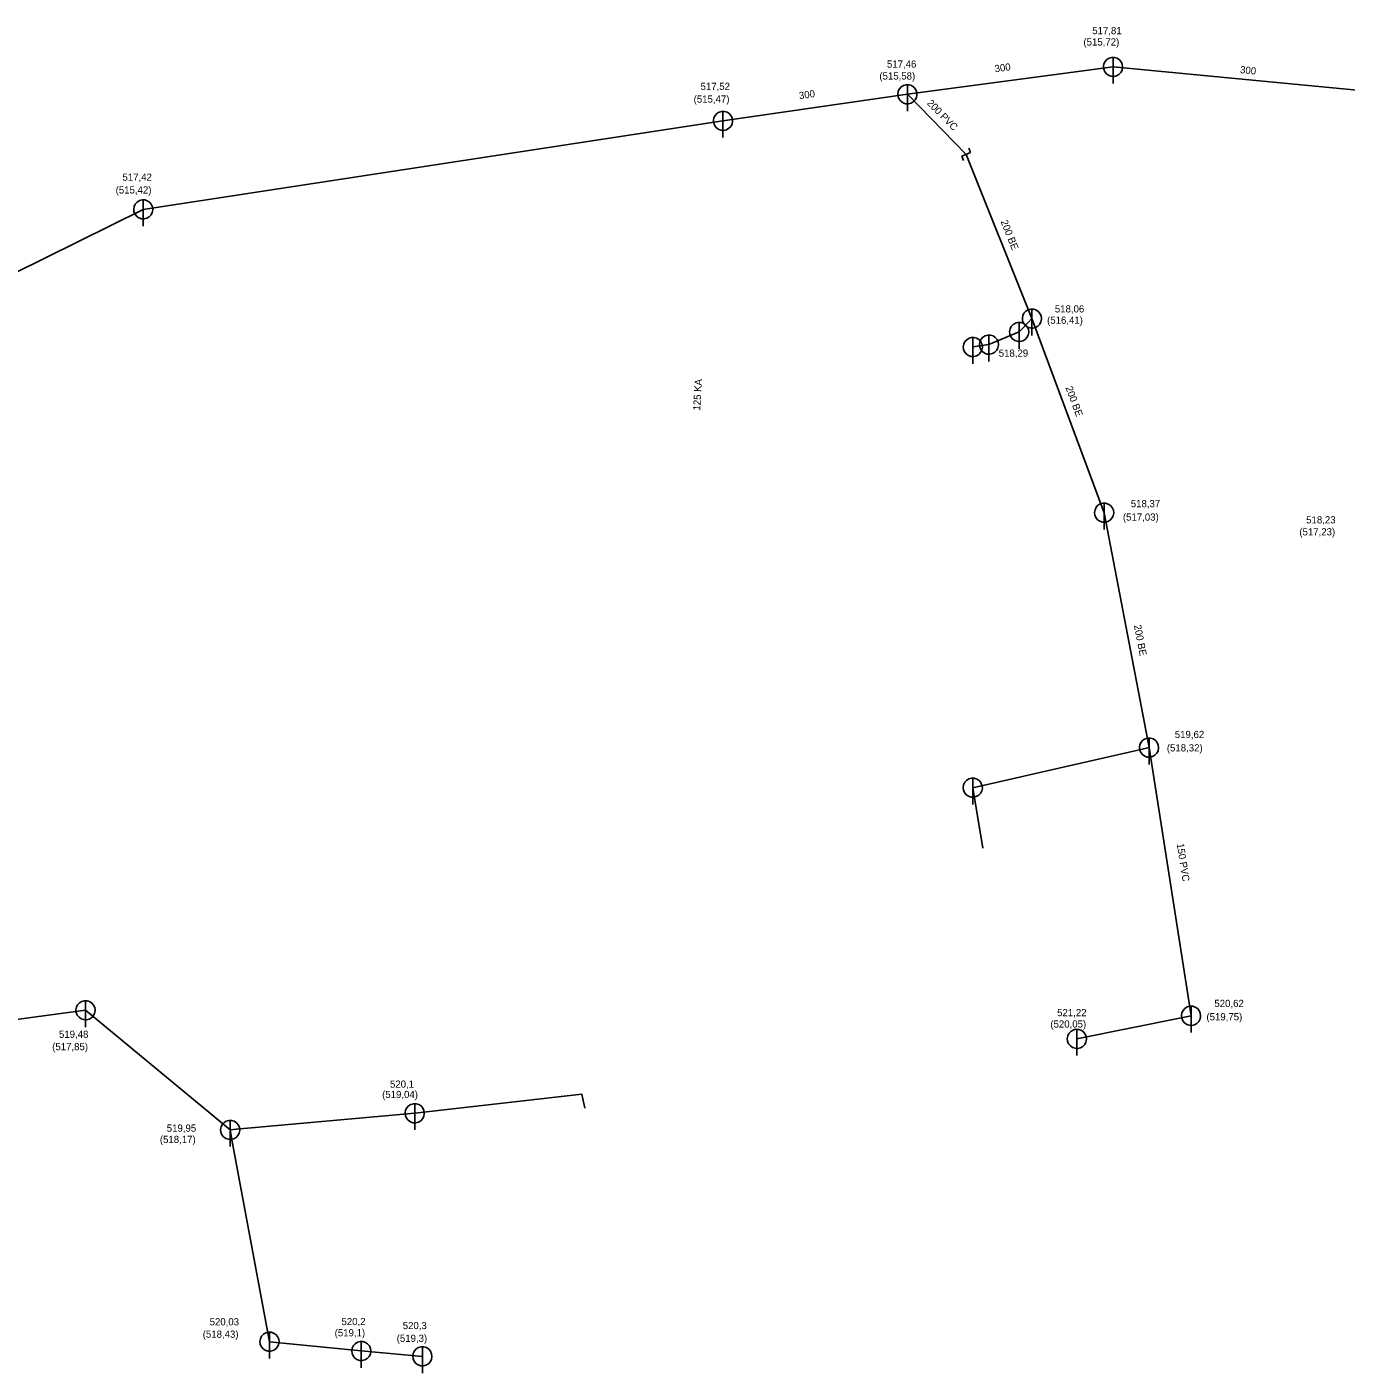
# Model space of a CAD drawing. Extents: x -476058 to -471893, y -1155786 to -1152000.
# Drawn here: x -474134.8 to -473997.2, y -1154043.8 to -1153903.4 of the extents above; entities that cross this region are included whole.
import ezdxf

# ---------------------------------------------------------------- set-up
doc = ezdxf.new("R2010")
doc.units = 0
for name, color, linetype in [('Vrstva 10', 7, 'Continuous'), ('Vrstva 18', 7, 'Continuous'), ('Vrstva 19', 7, 'Continuous'), ('Vrstva 3', 7, 'Continuous'), ('Vrstva 4', 7, 'Continuous'), ('Vrstva 45', 7, 'Continuous'), ('Vrstva 50', 7, 'Continuous'), ('Vrstva 51', 7, 'Continuous')]:
    doc.layers.add(name, color=color, linetype=linetype)

msp = doc.modelspace()

# ---------------------------------------------------------------- linework, layer by layer
at = {"layer": 'Vrstva 10'}
for p, q in [((-474021.48, -1153906.57), (-474021.48, -1153909.32)), ((-474042.93, -1153909.43), (-474042.93, -1153912.18)), ((-474062.16, -1153912.2), (-474062.16, -1153914.95)), ((-474036.33, -1153916.51), (-474036.52, -1153916.05)), ((-474037.26, -1153916.88), (-474036.33, -1153916.51)), ((-474037.26, -1153916.88), (-474037.07, -1153917.35)), ((-474122.62, -1153921.44), (-474122.62, -1153924.19)), ((-474029.94, -1153932.83), (-474029.94, -1153935.58)), ((-474031.27, -1153934.22), (-474031.27, -1153936.97)), ((-474036.1, -1153935.79), (-474036.1, -1153938.54)), ((-474034.42, -1153935.55), (-474034.42, -1153938.3)), ((-474022.41, -1153953.08), (-474022.41, -1153955.83)), ((-474017.73, -1153977.59), (-474017.73, -1153980.34)), ((-474036.11, -1153981.77), (-474036.11, -1153984.52)), ((-474128.64, -1154004.99), (-474128.64, -1154007.74)), ((-474013.35, -1154005.57), (-474013.35, -1154008.32)), ((-474025.25, -1154007.97), (-474025.25, -1154010.72)), ((-474094.31, -1154015.73), (-474094.31, -1154018.48)), ((-474113.56, -1154017.47), (-474113.56, -1154020.22)), ((-474109.45, -1154039.57), (-474109.45, -1154042.32)), ((-474099.88, -1154040.54), (-474099.88, -1154043.29)), ((-474093.51, -1154041.1), (-474093.51, -1154043.84))]:
    msp.add_line(p, q, dxfattribs=at)
for points in [[(-474020.48, -1153907.57), (-474020.52, -1153907.29), (-474020.64, -1153907.03), (-474020.82, -1153906.82), (-474021.05, -1153906.67), (-474021.33, -1153906.58), (-474021.61, -1153906.58), (-474021.88, -1153906.65), (-474022.12, -1153906.8), (-474022.31, -1153907.01), (-474022.43, -1153907.26), (-474022.48, -1153907.54), (-474022.45, -1153907.82), (-474022.34, -1153908.08), (-474022.16, -1153908.3), (-474021.93, -1153908.46), (-474021.66, -1153908.55), (-474021.38, -1153908.57), (-474021.11, -1153908.5), (-474020.86, -1153908.36), (-474020.67, -1153908.15), (-474020.54, -1153907.9), (-474020.48, -1153907.63), (-474020.48, -1153907.57)], [(-474041.93, -1153910.43), (-474041.97, -1153910.15), (-474042.09, -1153909.89), (-474042.27, -1153909.68), (-474042.5, -1153909.52), (-474042.77, -1153909.44), (-474043.06, -1153909.44), (-474043.33, -1153909.51), (-474043.57, -1153909.66), (-474043.76, -1153909.87), (-474043.88, -1153910.12), (-474043.93, -1153910.4), (-474043.9, -1153910.68), (-474043.79, -1153910.94), (-474043.61, -1153911.16), (-474043.38, -1153911.32), (-474043.11, -1153911.41), (-474042.83, -1153911.42), (-474042.55, -1153911.35), (-474042.31, -1153911.21), (-474042.12, -1153911.01), (-474041.99, -1153910.76), (-474041.93, -1153910.48), (-474041.93, -1153910.43)], [(-474061.16, -1153913.2), (-474061.2, -1153912.92), (-474061.32, -1153912.66), (-474061.5, -1153912.45), (-474061.74, -1153912.29), (-474062.01, -1153912.21), (-474062.29, -1153912.21), (-474062.56, -1153912.28), (-474062.8, -1153912.43), (-474062.99, -1153912.64), (-474063.11, -1153912.89), (-474063.16, -1153913.17), (-474063.13, -1153913.45), (-474063.02, -1153913.71), (-474062.84, -1153913.93), (-474062.61, -1153914.09), (-474062.34, -1153914.18), (-474062.06, -1153914.19), (-474061.79, -1153914.12), (-474061.54, -1153913.98), (-474061.35, -1153913.78), (-474061.22, -1153913.53), (-474061.16, -1153913.25), (-474061.16, -1153913.2)], [(-474121.62, -1153922.44), (-474121.66, -1153922.16), (-474121.78, -1153921.9), (-474121.96, -1153921.69), (-474122.2, -1153921.53), (-474122.47, -1153921.45), (-474122.75, -1153921.45), (-474123.02, -1153921.52), (-474123.26, -1153921.67), (-474123.45, -1153921.88), (-474123.57, -1153922.13), (-474123.62, -1153922.41), (-474123.59, -1153922.69), (-474123.48, -1153922.95), (-474123.3, -1153923.17), (-474123.07, -1153923.33), (-474122.8, -1153923.42), (-474122.52, -1153923.43), (-474122.25, -1153923.36), (-474122, -1153923.22), (-474121.81, -1153923.02), (-474121.68, -1153922.77), (-474121.62, -1153922.49), (-474121.62, -1153922.44)], [(-474028.94, -1153933.83), (-474028.98, -1153933.55), (-474029.1, -1153933.29), (-474029.28, -1153933.08), (-474029.52, -1153932.93), (-474029.79, -1153932.84), (-474030.07, -1153932.84), (-474030.34, -1153932.91), (-474030.58, -1153933.06), (-474030.77, -1153933.27), (-474030.89, -1153933.52), (-474030.94, -1153933.8), (-474030.91, -1153934.08), (-474030.8, -1153934.34), (-474030.62, -1153934.56), (-474030.39, -1153934.72), (-474030.12, -1153934.81), (-474029.84, -1153934.83), (-474029.57, -1153934.76), (-474029.32, -1153934.62), (-474029.13, -1153934.41), (-474029, -1153934.16), (-474028.94, -1153933.89), (-474028.94, -1153933.83)], [(-474030.27, -1153935.22), (-474030.31, -1153934.94), (-474030.43, -1153934.68), (-474030.61, -1153934.47), (-474030.85, -1153934.31), (-474031.11, -1153934.23), (-474031.4, -1153934.23), (-474031.67, -1153934.3), (-474031.91, -1153934.45), (-474032.1, -1153934.66), (-474032.22, -1153934.91), (-474032.27, -1153935.19), (-474032.24, -1153935.47), (-474032.13, -1153935.73), (-474031.95, -1153935.95), (-474031.72, -1153936.11), (-474031.45, -1153936.2), (-474031.17, -1153936.22), (-474030.9, -1153936.15), (-474030.65, -1153936.01), (-474030.46, -1153935.8), (-474030.33, -1153935.55), (-474030.27, -1153935.28), (-474030.27, -1153935.22)], [(-474035.1, -1153936.79), (-474035.14, -1153936.52), (-474035.26, -1153936.26), (-474035.44, -1153936.04), (-474035.68, -1153935.89), (-474035.95, -1153935.81), (-474036.23, -1153935.8), (-474036.5, -1153935.88), (-474036.74, -1153936.03), (-474036.93, -1153936.23), (-474037.05, -1153936.49), (-474037.1, -1153936.77), (-474037.07, -1153937.05), (-474036.96, -1153937.31), (-474036.78, -1153937.53), (-474036.55, -1153937.69), (-474036.29, -1153937.78), (-474036, -1153937.79), (-474035.73, -1153937.72), (-474035.48, -1153937.58), (-474035.29, -1153937.38), (-474035.16, -1153937.13), (-474035.1, -1153936.85), (-474035.1, -1153936.79)], [(-474033.42, -1153936.55), (-474033.46, -1153936.27), (-474033.58, -1153936.01), (-474033.76, -1153935.8), (-474033.99, -1153935.64), (-474034.27, -1153935.56), (-474034.55, -1153935.56), (-474034.82, -1153935.63), (-474035.06, -1153935.78), (-474035.25, -1153935.99), (-474035.37, -1153936.24), (-474035.42, -1153936.52), (-474035.39, -1153936.8), (-474035.28, -1153937.06), (-474035.1, -1153937.28), (-474034.87, -1153937.44), (-474034.6, -1153937.53), (-474034.32, -1153937.54), (-474034.05, -1153937.48), (-474033.8, -1153937.33), (-474033.61, -1153937.13), (-474033.48, -1153936.88), (-474033.42, -1153936.6), (-474033.42, -1153936.55)], [(-474021.41, -1153954.08), (-474021.45, -1153953.8), (-474021.57, -1153953.54), (-474021.75, -1153953.33), (-474021.98, -1153953.18), (-474022.26, -1153953.09), (-474022.54, -1153953.09), (-474022.81, -1153953.16), (-474023.05, -1153953.31), (-474023.24, -1153953.52), (-474023.36, -1153953.77), (-474023.41, -1153954.05), (-474023.38, -1153954.33), (-474023.27, -1153954.59), (-474023.09, -1153954.81), (-474022.86, -1153954.97), (-474022.59, -1153955.06), (-474022.31, -1153955.08), (-474022.04, -1153955.01), (-474021.79, -1153954.87), (-474021.6, -1153954.66), (-474021.47, -1153954.41), (-474021.41, -1153954.14), (-474021.41, -1153954.08)], [(-474016.73, -1153978.59), (-474016.77, -1153978.31), (-474016.89, -1153978.05), (-474017.07, -1153977.84), (-474017.3, -1153977.69), (-474017.58, -1153977.6), (-474017.86, -1153977.6), (-474018.13, -1153977.67), (-474018.37, -1153977.82), (-474018.56, -1153978.03), (-474018.68, -1153978.28), (-474018.73, -1153978.56), (-474018.7, -1153978.84), (-474018.59, -1153979.1), (-474018.41, -1153979.32), (-474018.18, -1153979.48), (-474017.91, -1153979.57), (-474017.63, -1153979.59), (-474017.36, -1153979.52), (-474017.11, -1153979.38), (-474016.92, -1153979.17), (-474016.79, -1153978.92), (-474016.73, -1153978.65), (-474016.73, -1153978.59)], [(-474035.11, -1153982.77), (-474035.15, -1153982.5), (-474035.27, -1153982.24), (-474035.45, -1153982.02), (-474035.69, -1153981.87), (-474035.96, -1153981.79), (-474036.24, -1153981.78), (-474036.51, -1153981.86), (-474036.75, -1153982.01), (-474036.94, -1153982.21), (-474037.06, -1153982.47), (-474037.11, -1153982.75), (-474037.08, -1153983.03), (-474036.97, -1153983.29), (-474036.79, -1153983.51), (-474036.56, -1153983.67), (-474036.29, -1153983.76), (-474036.01, -1153983.77), (-474035.74, -1153983.7), (-474035.49, -1153983.56), (-474035.3, -1153983.36), (-474035.17, -1153983.11), (-474035.11, -1153982.83), (-474035.11, -1153982.77)], [(-474127.64, -1154005.99), (-474127.68, -1154005.71), (-474127.8, -1154005.45), (-474127.98, -1154005.24), (-474128.22, -1154005.08), (-474128.48, -1154005), (-474128.77, -1154005), (-474129.04, -1154005.07), (-474129.28, -1154005.22), (-474129.47, -1154005.43), (-474129.59, -1154005.68), (-474129.64, -1154005.96), (-474129.61, -1154006.24), (-474129.5, -1154006.5), (-474129.32, -1154006.72), (-474129.09, -1154006.88), (-474128.82, -1154006.97), (-474128.54, -1154006.99), (-474128.27, -1154006.92), (-474128.02, -1154006.78), (-474127.83, -1154006.57), (-474127.7, -1154006.32), (-474127.64, -1154006.05), (-474127.64, -1154005.99)], [(-474012.35, -1154006.57), (-474012.39, -1154006.29), (-474012.51, -1154006.03), (-474012.69, -1154005.82), (-474012.92, -1154005.67), (-474013.2, -1154005.58), (-474013.48, -1154005.58), (-474013.75, -1154005.65), (-474013.99, -1154005.8), (-474014.18, -1154006.01), (-474014.3, -1154006.26), (-474014.35, -1154006.54), (-474014.32, -1154006.82), (-474014.21, -1154007.08), (-474014.03, -1154007.3), (-474013.8, -1154007.46), (-474013.53, -1154007.55), (-474013.25, -1154007.57), (-474012.98, -1154007.5), (-474012.73, -1154007.36), (-474012.54, -1154007.15), (-474012.41, -1154006.9), (-474012.35, -1154006.63), (-474012.35, -1154006.57)], [(-474024.25, -1154008.97), (-474024.29, -1154008.7), (-474024.41, -1154008.44), (-474024.59, -1154008.22), (-474024.83, -1154008.07), (-474025.1, -1154007.99), (-474025.38, -1154007.98), (-474025.65, -1154008.06), (-474025.89, -1154008.21), (-474026.08, -1154008.41), (-474026.2, -1154008.67), (-474026.25, -1154008.95), (-474026.22, -1154009.23), (-474026.11, -1154009.49), (-474025.93, -1154009.71), (-474025.7, -1154009.87), (-474025.43, -1154009.96), (-474025.15, -1154009.97), (-474024.88, -1154009.9), (-474024.63, -1154009.76), (-474024.44, -1154009.56), (-474024.31, -1154009.31), (-474024.25, -1154009.03), (-474024.25, -1154008.97)], [(-474093.31, -1154016.73), (-474093.35, -1154016.46), (-474093.46, -1154016.2), (-474093.65, -1154015.98), (-474093.88, -1154015.83), (-474094.15, -1154015.75), (-474094.43, -1154015.74), (-474094.71, -1154015.82), (-474094.95, -1154015.97), (-474095.14, -1154016.17), (-474095.26, -1154016.43), (-474095.31, -1154016.71), (-474095.27, -1154016.99), (-474095.17, -1154017.25), (-474094.99, -1154017.47), (-474094.76, -1154017.63), (-474094.49, -1154017.72), (-474094.21, -1154017.73), (-474093.93, -1154017.66), (-474093.69, -1154017.52), (-474093.49, -1154017.32), (-474093.36, -1154017.07), (-474093.31, -1154016.79), (-474093.31, -1154016.73)], [(-474112.56, -1154018.47), (-474112.6, -1154018.19), (-474112.72, -1154017.93), (-474112.9, -1154017.72), (-474113.14, -1154017.56), (-474113.41, -1154017.48), (-474113.69, -1154017.48), (-474113.96, -1154017.55), (-474114.2, -1154017.7), (-474114.39, -1154017.91), (-474114.51, -1154018.16), (-474114.56, -1154018.44), (-474114.53, -1154018.72), (-474114.42, -1154018.98), (-474114.24, -1154019.2), (-474114.01, -1154019.36), (-474113.74, -1154019.45), (-474113.46, -1154019.47), (-474113.19, -1154019.4), (-474112.94, -1154019.26), (-474112.75, -1154019.05), (-474112.62, -1154018.8), (-474112.56, -1154018.53), (-474112.56, -1154018.47)], [(-474108.45, -1154040.57), (-474108.49, -1154040.29), (-474108.61, -1154040.03), (-474108.79, -1154039.82), (-474109.03, -1154039.67), (-474109.29, -1154039.58), (-474109.58, -1154039.58), (-474109.85, -1154039.65), (-474110.09, -1154039.8), (-474110.28, -1154040.01), (-474110.4, -1154040.26), (-474110.45, -1154040.54), (-474110.42, -1154040.82), (-474110.31, -1154041.08), (-474110.13, -1154041.3), (-474109.9, -1154041.46), (-474109.63, -1154041.55), (-474109.35, -1154041.57), (-474109.08, -1154041.5), (-474108.83, -1154041.36), (-474108.64, -1154041.15), (-474108.51, -1154040.9), (-474108.45, -1154040.63), (-474108.45, -1154040.57)], [(-474098.88, -1154041.54), (-474098.92, -1154041.27), (-474099.03, -1154041.01), (-474099.22, -1154040.79), (-474099.45, -1154040.64), (-474099.72, -1154040.56), (-474100.01, -1154040.55), (-474100.28, -1154040.63), (-474100.52, -1154040.78), (-474100.71, -1154040.98), (-474100.83, -1154041.24), (-474100.88, -1154041.52), (-474100.85, -1154041.8), (-474100.74, -1154042.06), (-474100.56, -1154042.28), (-474100.33, -1154042.44), (-474100.06, -1154042.53), (-474099.78, -1154042.54), (-474099.5, -1154042.47), (-474099.26, -1154042.33), (-474099.07, -1154042.13), (-474098.93, -1154041.88), (-474098.88, -1154041.6), (-474098.88, -1154041.54)], [(-474092.51, -1154042.1), (-474092.55, -1154041.82), (-474092.67, -1154041.56), (-474092.85, -1154041.34), (-474093.09, -1154041.19), (-474093.36, -1154041.11), (-474093.64, -1154041.1), (-474093.91, -1154041.18), (-474094.15, -1154041.33), (-474094.34, -1154041.54), (-474094.46, -1154041.79), (-474094.51, -1154042.07), (-474094.48, -1154042.35), (-474094.37, -1154042.61), (-474094.19, -1154042.83), (-474093.96, -1154042.99), (-474093.69, -1154043.08), (-474093.41, -1154043.09), (-474093.14, -1154043.02), (-474092.89, -1154042.88), (-474092.7, -1154042.68), (-474092.57, -1154042.43), (-474092.51, -1154042.15), (-474092.51, -1154042.1)]]:
    msp.add_lwpolyline(points, dxfattribs=at)
at = {"layer": 'Vrstva 45'}
for points in [[(-474021.48, -1153907.57), (-474042.93, -1153910.43)], [(-473988.42, -1153910.73), (-474021.48, -1153907.57)], [(-474042.93, -1153910.43), (-474062.16, -1153913.2)], [(-474036.79, -1153916.7), (-474042.93, -1153910.43)], [(-474062.16, -1153913.2), (-474122.62, -1153922.44)], [(-474029.94, -1153933.83), (-474036.79, -1153916.7)], [(-474122.62, -1153922.44), (-474169.87, -1153945.83)], [(-474022.41, -1153954.08), (-474029.94, -1153933.83)], [(-474017.73, -1153978.59), (-474022.41, -1153954.08)], [(-474013.35, -1154006.57), (-474017.73, -1153978.59)], [(-474128.64, -1154005.99), (-474160.1, -1154010.23)], [(-474113.56, -1154018.47), (-474128.64, -1154005.99)]]:
    msp.add_lwpolyline(points, dxfattribs=at)
at = {"layer": 'Vrstva 50'}
for points in [[(-474029.94, -1153933.83), (-474030.73, -1153934.66), (-474031.27, -1153935.22), (-474034.42, -1153936.55), (-474036.1, -1153936.79)], [(-474027.89, -1153980.9), (-474018.27, -1153978.71), (-474017.73, -1153978.59)], [(-474030.79, -1153981.56), (-474036.11, -1153982.77)], [(-474027.89, -1153980.9), (-474030.79, -1153981.56)], [(-474025.25, -1154008.97), (-474014.04, -1154006.71), (-474013.35, -1154006.57)], [(-474113.56, -1154018.47), (-474112.9, -1154018.41), (-474094.31, -1154016.73)], [(-474113.34, -1154019.67), (-474113.56, -1154018.47)], [(-474109.45, -1154040.57), (-474113.34, -1154019.67)], [(-474099.88, -1154041.54), (-474109.45, -1154040.57)]]:
    msp.add_lwpolyline(points, dxfattribs=at)
at = {"layer": 'Vrstva 51'}
for points in [[(-474036.11, -1153982.77), (-474035.07, -1153989.09)], [(-474094.31, -1154016.73), (-474076.87, -1154014.75), (-474076.58, -1154016.22)], [(-474099.88, -1154041.54), (-474093.51, -1154042.1)]]:
    msp.add_lwpolyline(points, dxfattribs=at)

# ---------------------------------------------------------------- texts
at = {"layer": 'Vrstva 18'}
for s, rotation, p in [('300 ', 7.5871, (-474033.78, -1153908.14)), ('300 ', 354.3683, (-474008.26, -1153908.22)), ('300 ', 8.196, (-474054.18, -1153910.95)), ('200 PVC', 314.3764, (-474040.94, -1153911.41)), ('200 BE', 291.8054, (-474033.22, -1153923.7)), ('200 BE', 290.3977, (-474026.45, -1153941.04)), ('200 BE', 280.8101, (-474019.3, -1153965.84)), ('150 PVC', 278.8969, (-474014.84, -1153988.63))]:
    msp.add_text(s, height=0.75, rotation=rotation, dxfattribs=at).set_placement(p)
at = {"layer": 'Vrstva 19'}
msp.add_text('125 KA', height=0.75, rotation=86.6728, dxfattribs=at).set_placement((-474064.54, -1153943.44))
at = {"layer": 'Vrstva 3'}
for s, p in [('517,81', (-474023.65, -1153904.16)), ('517,46', (-474045.06, -1153907.65)), ('517,52', (-474064.5, -1153909.98)), ('517,42', (-474124.79, -1153919.45)), ('518,06', (-474027.55, -1153933.19)), ('518,29', (-474033.4, -1153937.81)), ('518,37', (-474019.63, -1153953.51)), ('518,23', (-474001.34, -1153955.2)), ('519,62', (-474015.04, -1153977.59)), ('521,22', (-474027.31, -1154006.61)), ('520,62', (-474010.91, -1154005.65)), ('519,48', (-474131.41, -1154008.87)), ('520,1', (-474096.89, -1154014.07)), ('519,95', (-474120.17, -1154018.66)), ('520,03', (-474115.7, -1154038.87)), ('520,2', (-474101.95, -1154038.84)), ('520,3', (-474095.56, -1154039.26))]:
    msp.add_text(s, height=0.75, dxfattribs=at).set_placement(p)
at = {"layer": 'Vrstva 4'}
for s, p in [('(515,72)', (-474024.57, -1153905.34)), ('(515,58)', (-474045.85, -1153908.89)), ('(515,47)', (-474065.22, -1153911.3)), ('(515,42)', (-474125.5, -1153920.78)), ('(516,41)', (-474028.36, -1153934.37)), ('(517,03)', (-474020.45, -1153954.91)), ('(517,23)', (-474002.05, -1153956.45)), ('(518,32)', (-474015.87, -1153978.99)), ('(520,05)', (-474028.02, -1154007.8)), ('(519,75)', (-474011.74, -1154007.04)), ('(517,85)', (-474132.12, -1154010.16)), ('(519,04)', (-474097.71, -1154015.15)), ('(518,17)', (-474120.89, -1154019.84)), ('(518,43)', (-474116.42, -1154040.16)), ('(519,1)', (-474102.66, -1154040.01)), ('(519,3)', (-474096.19, -1154040.59))]:
    msp.add_text(s, height=0.75, dxfattribs=at).set_placement(p)

doc.saveas('drawing.dxf')
